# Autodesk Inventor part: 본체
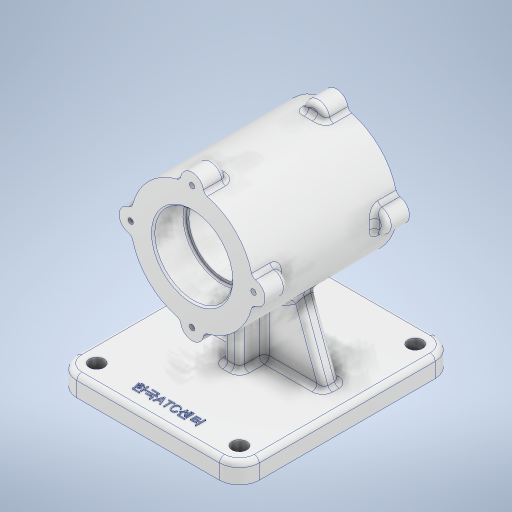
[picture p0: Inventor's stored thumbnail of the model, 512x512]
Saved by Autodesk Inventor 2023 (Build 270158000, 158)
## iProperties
Created: 2023-08
Part Number: 본체
Material: 알루미늄 6061
Document SubType Name: Modeling
Designer: asung
Density: 2.7 g/cm^3
Appearance: 알루미늄 - 평지
Author: asung
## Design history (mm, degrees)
sketch "스케치1"
  geometry: L1 (43, 65)-(-43, 65); L2 (-55, 53)-(-55, -53); L3 (-43, -65)-(43, -65); L4 (55, -53)-(55, 53); L5 (55, 65)-(-55, -65); L6 (-55, 65)-(55, -65); C1 r 4.5 at (43, 53); C2 r 4.5 at (43, -53); C3 r 4.5 at (-43, 53); C4 r 4.5 at (-43, -53); A1 r 12 centre (-43, 53) between (-43, 65) and (-55, 53); A2 r 12 centre (-43, -53) between (-55, -53) and (-43, -65); A3 r 12 centre (43, -53) between (43, -65) and (55, -53); A4 r 12 centre (43, 53) between (55, 53) and (43, 65); 1 further point
  constraints: 12 end point, 8 centre point, 8 point on circle, 8 point on line, 8 tangent, 4 coincident, 3 equal radius, 2 midpoint, 2 parallel, 1 horizontal, 1 perpendicular
  dimensions: "d0" = 110 distance of L6.end L5.end; "d1" = 130 distance of L5.end L6.start; "d2" = 12 radius of A1; "d3" = 9 diameter of C1; "d4" = 9 diameter of C2; "d5" = 9 diameter of C3; "d6" = 9 diameter of C4
extrude "돌출1" new body sketch "스케치1" distance "d7" = 12; taper "d8" = 0 deg
fillet "모깎기1" dims "d9" = 3
sketch "스케치2"
  geometry: L1 (12, 62)-(12, -62) reference; L2 (9, -65)-(0, -65) reference; L3 (0, -65)-(0, 65) reference; L4 (0, 65)-(9, 65) reference; L5 (0, 53)-(0, 65) reference; L6 (0, 65)-(0, -5); L7 (0, -53)-(0, 53) reference; L8 (0, 65)-(0, -5); L9 (0, -5)-(82, -5); L10 (82, 38.5)-(82, -48.5); L11 (82, 38.5)-(119, 38.5); L12 (119, 38.5)-(119, -48.5); L13 (119, -48.5)-(82, -48.5); A1 r 3 centre (9, 62) between (12, 62) and (9, 65) reference; A2 r 3 centre (9, -62) between (9, -65) and (12, -62) reference; 1 further point
  constraints: 14 end point, 2 perpendicular, 2 vertical, 1 horizontal, 1 midpoint, 1 point on line
  dimensions: "d12" = 70 distance of L3.end L6.end; "d13" = 82 distance of L9.end L6.end; "d14" = 87 distance of L10.start L10.end; "d15" = 37 distance of L10.start L11.end; "d16" = 87 distance of L11.end L12.end
  node "절단 모서리 투영1"
sketch "스케치3"
  geometry: 1 further point
sketch "스케치4"
  geometry: 1 further point
revolve "회전1" stored, may be unused: angle "d17" = 90 deg
sketch "스케치5"
  geometry: C1 r 37 at (0, 0) reference; 2 further points
  constraints: 1 coincident
hole "구멍1" sketch "스케치5" at (0, 0) diameter "d18" = 42; stored, may be unused: countersink angle "d22" = 90 deg, drill point angle "d24" = 0 deg; dims "d19" = 10, "d20" = 47, "d21" = 19, "d23" = 87
sketch "스케치6"
  geometry: C1 r 37 at (0, 0) reference; 2 further points
  constraints: 1 coincident
hole "구멍2" sketch "스케치6" at (0, 0) diameter "d25" = 42; stored, may be unused: countersink angle "d29" = 90 deg, drill point angle "d31" = 0 deg; dims "d26" = 6, "d27" = 47, "d28" = 19, "d30" = 87
chamfer "모따기1" distance "d32" = 1; stored, may be unused: second distance "d33" = 2, angle "d34" = 45 deg
fillet "모깎기2" dims "d35" = 1
sketch "스케치7"
  geometry: 1 further point
sketch "스케치8"
  geometry: C1 r 37 at (0, 0) reference; C2 r 24.5 at (0, 0) reference; C3 r 7 at (0, 37); 2 further points
  constraints: 1 centre point, 1 vertical alignment, 1 other
  dimensions: "d36" = 14 diameter of C3
extrude "돌출2" join sketch "스케치8" distance "d37" = 14; taper "d38" = 0 deg
fillet "모깎기3" dims "d39" = 3
sketch "스케치9"
  geometry: C1 r 24.5 at (0, 0) reference; C2 r 7 at (0, 37); A1 r 37 centre (0, 0) between (-3.994, 36.784) and (3.994, 36.784) reference; A2 r 4 centre (0, 37) between (3.994, 36.784) and (-3.994, 36.784) reference; 1 further point
  constraints: 1 centre point, 1 coincident
  dimensions: "d43" = 14 diameter of C2
extrude "돌출3" join sketch "스케치9" distance "d44" = 14; taper "d45" = 0 deg
fillet "모깎기4" dims "d46" = 3
sketch "스케치10"
  geometry: A1 r 7 centre (0, 0) between (6.969, -0.662) and (-6.969, -0.662) reference; 2 further points
  constraints: 1 coincident
hole "구멍3" sketch "스케치10" at (0, 0) diameter "d50" = 3.242; stored, may be unused: countersink angle "d54" = 90 deg, drill point angle "d56" = 118 deg; dims "d51" = 8, "d52" = 47, "d53" = 19, "d55" = 10
sketch "스케치11"
  geometry: A1 r 7 centre (0, 0) between (6.969, -0.662) and (-6.969, -0.662) reference; 2 further points
  constraints: 1 coincident
hole "구멍4" sketch "스케치11" at (0, 0) diameter "d60" = 3.242; stored, may be unused: countersink angle "d64" = 90 deg, drill point angle "d66" = 118 deg; dims "d61" = 8, "d62" = 4, "d63" = 2, "d65" = 10
sketch "스케치12"
  geometry: L1 (52, -53)-(52, 53) reference; L2 (43, 62)-(-43, 62) reference; L3 (-52, 53)-(-52, -53) reference; L4 (-43, -62)-(43, -62) reference; L5 (-43, -65)-(43, -65) reference; L6 (-55, 53)-(-55, -53) reference; L7 (55, -53)-(55, 53) reference; L8 (-5, 25)-(-5, -15); L9 (5, 25)-(5, -15); L10 (-55, -15)-(-52, -15); L11 (-55, 5)-(-52, 5); L12 (-55, 25)-(-52, 25); L13 (-5, 25)-(5, 25); L14 (52, 25)-(55, 25); L15 (52, 5)-(55, 5); L16 (-5, -15)-(5, -15); L17 (52, -15)-(55, -15); C1 r 4.5 at (-43, -53) reference; C2 r 4.5 at (-43, 53) reference; C3 r 4.5 at (43, -53) reference; C4 r 4.5 at (43, 53) reference; A1 r 9 centre (43, -53) between (43, -62) and (52, -53) reference; A2 r 9 centre (43, 53) between (52, 53) and (43, 62) reference; A3 r 9 centre (-43, 53) between (-43, 62) and (-52, 53) reference; A4 r 9 centre (-43, -53) between (-52, -53) and (-43, -62) reference
  constraints: 20 end point, 14 parallel, 8 point on line
  node "절단 모서리 투영2"
sketch "스케치13"
  geometry: 1 further point
node "작업 평면2"
sketch "스케치14"
  geometry: L1 (-9, 12)-(95, 12) reference; L2 (98, 9)-(98, 0) reference; L3 (98, 0)-(-12, 0) reference; L4 (-12, 0)-(-12, 9) reference; L5 (2, 12)-(19.068, 58.893); L6 (84, 12)-(67.201, 58.155); C1 r 37 at (43, 82) reference; C2 r 21 at (43, 82) reference; A1 r 3 centre (-9, 9) between (-9, 12) and (-12, 9) reference; A2 r 3 centre (95, 9) between (98, 9) and (95, 12) reference; 2 further points
  constraints: 4 end point, 1 midpoint, 1 point on line
  dimensions: "d78" = 14 distance from line of L4 L5.start; "d79" = 14 horizontal distance of point (98, 4.5) L6.start; "d80" = 110 deg angle of L1 L5
  node "절단 모서리 투영3"
sketch "스케치15"
  geometry: L1 (0, -64.567)-(0, 5.433); L2 (0, 5.433)-(-55, 5.433); L3 (-55, 53)-(-55, -53) reference; L4 (0, 5.433)-(55, 5.433); L5 (55, -53)-(55, 53) reference; 1 further point
  constraints: 6 end point, 3 point on line, 1 horizontal, 1 vertical
  dimensions: "d96" = 70 distance of L1.start L1.end
extrude "돌출5" join sketch "스케치12" stored distance "d106" = 10; taper "d107" = 0 deg
feature "리브3" dims "d108" = 1, "d109" = 10, "d110" = 0, "d111" = 0, "d112" = 1, "d113" = 1
feature "리브4" dims "d114" = 1, "d115" = 10, "d116" = 0, "d117" = 0, "d118" = 1, "d119" = 1
fillet "모깎기7" dims "d120" = 3
fillet "모깎기8" dims "d121" = 3
sketch "스케치16"
  geometry: L1 (-43, -65)-(43, -65) reference; L2 (43, 65)-(-43, 65) reference; L3 (0, -65)-(0, 5); 2 further points
  constraints: 2 end point, 1 midpoint, 1 vertical, 1 other
  dimensions: "d124" = 70 distance of L3.start L3.end; "d125" = 58 vertical distance of point (0.301, -53) L3.end
feature "엠보싱1" sketch "스케치16" dims "d126" = 0.5, "d127" = 0
fillet "모깎기9" dims "d128" = 3
feature "Ҡ耀Ң耀Ҥ耀Ҧ耀Ҩ耀Ҫ耀Ҭ耀Ү耀" dims "d0" = 110, "d1" = 130, "d2" = 12, "d3" = 9, "d4" = 9, "d5" = 9, "d6" = 9, "d7" = 12, "d8" = 0, "d9" = 3, "d12" = 70, "d13" = 82, "d14" = 87, "d15" = 37, "d16" = 87, "d17" = 90 deg, "d18" = 42, "d19" = 10, "d20" = 47, "d21" = 19, "d22" = 90 deg, "d23" = 87, "d24" = 0, "d25" = 42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
node "솔리드1"
pattern_circular "원형 패턴1" dims angle "d41" = 360 deg
pattern_circular "원형 패턴2" dims angle "d48" = 360 deg
pattern_circular "원형 패턴3" dims angle "d58" = 360 deg
pattern_circular "원형 패턴4" dims angle "d68" = 360 deg
node "투영된 루프1"
node "투영된 루프2"
feature "A9D066F2-1C7D-4E18-AEED-F7BC21143FA4" dims "d18" = 42, "d19" = 10, "d20" = 47, "d21" = 19, "d22" = 90 deg, "d23" = 87, "d24" = 0
